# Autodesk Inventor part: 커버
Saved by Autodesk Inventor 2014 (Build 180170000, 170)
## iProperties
Created: 2026-04
Part Number: 커버
Material: 알루미늄 6061
Document SubType Name: Modeling
Designer: dg
Density: 2.71 g/cm^3
Appearance: 알루미늄 - 평지
Author: jhkim
Creation Date: 2026-03-27
Sending System: Autodesk Inventor 2026
Preprocessor: ST-DEVELOPER v20.1
Author: dg
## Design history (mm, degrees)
node "커버1"
node "솔리드1"
node "기준1"
